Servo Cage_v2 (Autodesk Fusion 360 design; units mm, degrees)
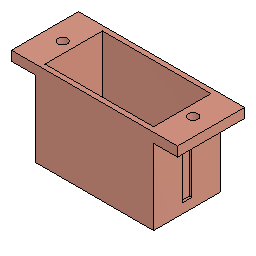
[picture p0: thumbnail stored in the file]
sketch "Sketch1" plane through (0, 0, 0) normal (0, 0, 1) x axis (1, 0, 0)
  line L1 (-11.35, -6) -> (11.35, -6)
  line L2 (-11.35, 6) -> (-11.35, -6)
  line L3 (11.35, 6) -> (-11.35, 6)
  line L4 (11.35, -6) -> (11.35, 6)
  line L5 (-11.35, 6) -> (11.35, -6)
  line L6 (11.35, 6) -> (-11.35, -6)
  line L7 (-16, 6) -> (-16, -6)
  line L8 (16, -6) -> (16, 6)
  line L9 (-16, 6) -> (16, -6)
  line L10 (16, 6) -> (-16, -6)
  line L11 (-12.35, 7) -> (12.35, 7)
  line L12 (-12.35, -7) -> (-12.35, 7)
  line L13 (12.35, -7) -> (-12.35, -7)
  line L14 (12.35, 7) -> (12.35, -7)
  line L15 (-12.35, -7) -> (12.35, 7)
  line L16 (12.35, -7) -> (-12.35, 7)
  line L17 (-16, 7) -> (16, 7)
  line L18 (-16, -7) -> (-16, 7)
  line L19 (16, -7) -> (-16, -7)
  line L20 (16, 7) -> (16, -7)
  line L21 (16, -7) -> (-16, 7)
  line L22 (11.35, 6) -> (-11.35, 6)
  line L23 (-11.35, -6) -> (11.35, -6)
  line L24 (-12.35, -5.4031) -> (16, 7)
  point P6 (0, 0)
  point P1 (0, 0)
  point P11 (0, 0)
  point P16 (0, 0)
  point P21 (0, 0)
  point P22 (-12.35, -5.4031)
  point P4 (-11.35, 6)
  point P5 (11.35, 6)
  point P3 (-11.35, -6)
  point P9 (-16, 6)
  point P10 (16, 6)
  point P8 (-16, -6)
  point P14 (-12.35, -7)
  point P15 (12.35, -7)
  point P13 (-12.35, 7)
  point P19 (-16, -7)
  point P20 (16, -7)
  point P18 (-16, 7)
  horizontal L1
  perpendicular L1 L2
  parallel L1 L3
  parallel L2 L4
  coincident L5 P6
  coincident L6 P6
  coincident P1 P6
  parallel L7 L8
  coincident L9 P11
  coincident L10 P11
  coincident P6 P11
  horizontal L11
  perpendicular L11 L12
  parallel L11 L13
  parallel L12 L14
  coincident L15 P16
  coincident L16 P16
  coincident P1 P16
  horizontal L17
  perpendicular L17 L18
  parallel L17 L19
  parallel L18 L20
  coincident P21 L24
  coincident L21 P21
  coincident P16 P21
  coincident L12 P22
  dimension "d1" distance P4 P5 = 22.7
  dimension "d2" distance P3 P4 = 12
  dimension "d3" distance P9 P10 = 32
  dimension "d4" distance P8 P9 = 12
  dimension "d5" distance P14 P15 = 24.7 (= "d1 + 2 mm")
  dimension "d6" distance P13 P14 = 14 (= "d2 + 2 mm")
  dimension "d7" distance P19 P20 = 32
  dimension "d8" distance P18 P19 = 14 (= "d2 + 2 mm")
extrude "Extrude1" new body sketch "Sketch1" profile of L1 L2 L3 L4 L23 L22 along normal blind 2
extrude "Extrude2" add sketch "Sketch1" profile of L1 L2 L3 L4 L23 L22 L11 L12 L13 L14 L17 L19 along normal blind 17.8 (= "15.8 mm + 2 mm")
sketch "Sketch2" plane through (12.35, 0, 0) normal (1, 0, 0) x axis (0, 1, 0)
  line L1 (7, 0) -> (-7, 0)
  line L2 (7, 17.8) -> (7, 0)
  line L3 (-7, 17.8) -> (7, 17.8)
  line L4 (-7, 0) -> (-7, 17.8)
  line L5 (7, 17.8) -> (-7, 17.8)
  line L6 (7, 15.8) -> (7, 17.8)
  line L7 (-7, 15.8) -> (7, 15.8)
  line L8 (-7, 17.8) -> (-7, 15.8)
  point P5 (-7, 17.8)
  point P6 (-7, 17.8)
  point P9 (-7, 15.8)
  horizontal L5
  vertical L6
  horizontal L7
  vertical L8
  coincident P5 P6
  dimension "d13" distance P6 P9 = 2
extrude "Extrude3" add sketch "Sketch2" profile of L2 L3 L4 L5 L6 L7 L8 along normal blind 5
sketch "Sketch3" plane through (0, 0, 17.8) normal (0, 0, 1) x axis (-1, 0, 0)
  line L1 (-11.35, 6) -> (-11.35, -6)
  line L2 (11.35, 6) -> (-11.35, 6)
  line L3 (11.35, -6) -> (11.35, 6)
  line L4 (-11.35, -6) -> (11.35, -6)
  line L5 (12.35, 7) -> (12.35, -7)
  line L6 (-17.35, 7) -> (12.35, 7)
  line L7 (-17.35, -7) -> (-17.35, 7)
  line L8 (12.35, -7) -> (-17.35, -7)
  circle C1 centre (-13.65, 0) radius 1
  point P10 (-13.65, 0)
  dimension "d16" diameter C1 = 2
  dimension "d17" distance L1 P10 = 2.3
extrude "Extrude4" cut sketch "Sketch3" profile of C1 against normal blind 2
mirror "Mirror1" mirrorStitchTolerance 0.1
sketch "Sketch4" plane through (-12.35, 0, 0) normal (-1, 0, 0) x axis (0, -1, 0)
  line L1 (-7, 15.8) -> (7, 15.8)
  line L2 (-7, 0) -> (-7, 15.8)
  line L3 (7, 0) -> (-7, 0)
  line L4 (7, 15.8) -> (7, 0)
  line L5 (7, 8.9) -> (-7, 8.9)
  line L6 (-1, 2) -> (1, 2)
  line L7 (-1, 15.8) -> (-1, 2)
  line L8 (1, 15.8) -> (-1, 15.8)
  line L9 (1, 2) -> (1, 15.8)
  line L10 (-1, 15.8) -> (1, 2)
  line L11 (1, 15.8) -> (-1, 2)
  point P6 (-7, 8.9)
  point P7 (7, 8.9)
  point P12 (0, 8.9)
  point P10 (-1, 15.8)
  point P11 (1, 15.8)
  point P9 (-1, 2)
  coincident L2 P6
  coincident L4 P7
  perpendicular L4 L5
  horizontal L6
  perpendicular L6 L7
  parallel L6 L8
  parallel L7 L9
  coincident L10 P12
  coincident L11 P12
  midpoint L5 P12
  dimension "d22" distance L3 L5 = 8.9 (= "( 15.8 / 2 ) * 1 mm + 1 mm")
  dimension "d23" distance P10 P11 = 2
  dimension "d24" distance P9 P10 = 13.8 (= "15.8 mm - 2 mm")
extrude "Extrude5" cut sketch "Sketch4" profile of L1 L3 L6 L7 L8 L9 against normal blind 0.5
mirror "Mirror2" mirrorStitchTolerance 0.1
